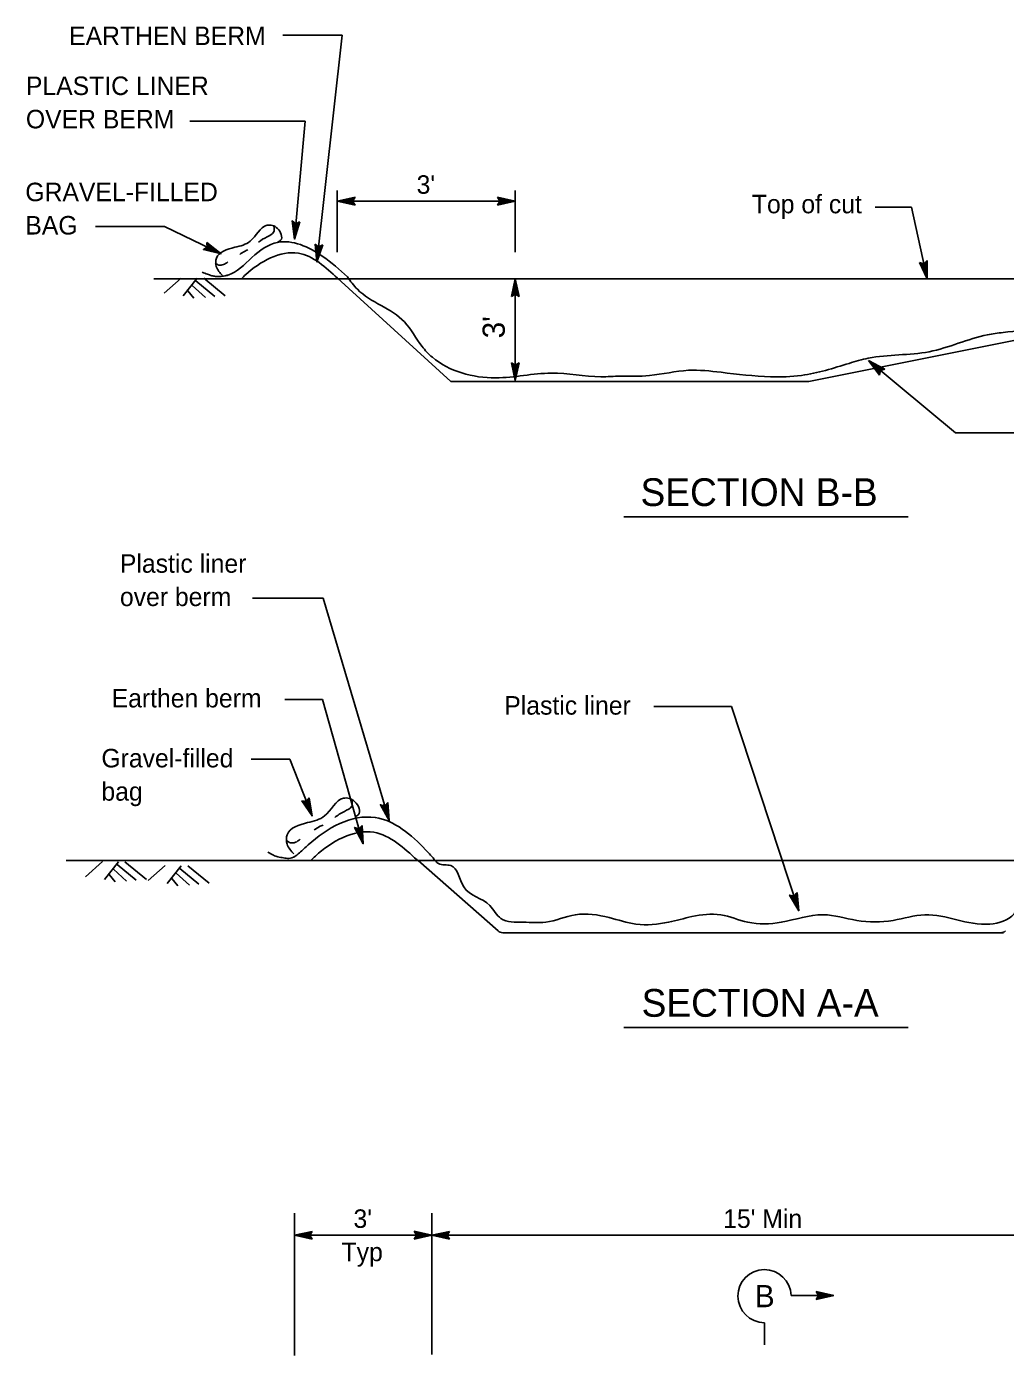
# Model space of a CAD drawing. Extents: x 6708826 to 6711089, y 1868571 to 1869537.
# Drawn here: x 6708825.9 to 6709143.3, y 1869106.3 to 1869537.2 of the extents above; entities that cross this region are included whole.
import ezdxf

# ---------------------------------------------------------------- set-up
doc = ezdxf.new("R2010")
doc.units = 0
for name, color, linetype in [('1 Control', 7, 'Continuous'), ('56 Stg 3 Anno', 7, 'Continuous'), ('57 Undefined', 7, 'Continuous'), ('59 Soundwall Ann', 7, 'Continuous'), ('60 Nongeo Data', 7, 'Continuous')]:
    doc.layers.add(name, color=color, linetype=linetype)

msp = doc.modelspace()

# ---------------------------------------------------------------- linework, layer by layer
at = {"layer": '1 Control'}
for p, q in [((6708911.99, 1869474.17), (6708911.99, 1869474.17)), ((6708914.54, 1869473.94), (6708914.54, 1869473.94)), ((6708912.74, 1869468.32), (6708912.74, 1869468.32)), ((6708883.21, 1869464.88), (6708883.21, 1869464.88)), ((6708884.32, 1869467.19), (6708884.32, 1869467.19)), ((6708888.96, 1869463.54), (6708888.96, 1869463.54)), ((6708917.57, 1869287.05), (6708917.57, 1869287.05)), ((6708915.18, 1869286.11), (6708915.18, 1869286.11)), ((6708940.64, 1869284.86), (6708940.64, 1869284.86)), ((6708943.09, 1869285.59), (6708943.09, 1869285.59)), ((6708918.48, 1869281.22), (6708918.48, 1869281.22)), ((6708934.74, 1869278.11), (6708934.74, 1869278.11)), ((6708943.5, 1869279.7), (6708943.5, 1869279.7)), ((6708932.27, 1869277.41), (6708932.27, 1869277.41)), ((6708935.07, 1869272.22), (6708935.07, 1869272.22)), ((6709073.32, 1869255.54), (6709073.32, 1869255.54)), ((6709075.75, 1869256.34), (6709075.75, 1869256.34)), ((6709076.33, 1869250.47), (6709076.33, 1869250.47))]:
    msp.add_line(p, q, dxfattribs=at)
for points in [[(6708914.54, 1869473.94), (6708912.74, 1869468.32), (6708911.99, 1869474.17), (6708912.31, 1869473.94), (6708912.86, 1869469.65), (6708914.19, 1869473.77), (6708913.83, 1869473.6), (6708912.98, 1869470.96), (6708912.63, 1869473.7), (6708912.95, 1869473.47), (6708913.1, 1869472.28), (6708913.47, 1869473.42), (6708913.19, 1869473.29), (6708911.99, 1869474.17), (6708913.19, 1869473.29)], [(6708884.32, 1869467.19), (6708888.96, 1869463.54), (6708883.21, 1869464.88), (6708883.54, 1869465.1), (6708887.75, 1869464.11), (6708884.36, 1869466.79), (6708884.39, 1869466.4), (6708886.57, 1869464.69), (6708883.87, 1869465.32), (6708884.21, 1869465.53), (6708885.37, 1869465.26), (6708884.43, 1869466), (6708884.46, 1869465.7), (6708883.21, 1869464.88), (6708884.46, 1869465.7)], [(6708917.57, 1869287.05), (6708918.48, 1869281.22), (6708915.18, 1869286.11), (6708915.58, 1869286.04), (6708917.99, 1869282.46), (6708917.33, 1869286.74), (6708917.08, 1869286.42), (6708917.51, 1869283.69), (6708915.97, 1869285.98), (6708916.36, 1869285.91), (6708917.03, 1869284.92), (6708916.84, 1869286.11), (6708916.65, 1869285.86), (6708915.18, 1869286.11), (6708916.65, 1869285.86)], [(6708943.09, 1869285.59), (6708943.5, 1869279.7), (6708940.64, 1869284.86), (6708941.02, 1869284.76), (6708943.12, 1869280.98), (6708942.83, 1869285.3), (6708942.56, 1869285.01), (6708942.75, 1869282.25), (6708941.41, 1869284.66), (6708941.79, 1869284.56), (6708942.37, 1869283.52), (6708942.29, 1869284.72), (6708942.08, 1869284.49), (6708940.64, 1869284.86), (6708942.08, 1869284.49)], [(6708934.74, 1869278.11), (6708935.07, 1869272.22), (6708932.27, 1869277.42), (6708932.66, 1869277.31), (6708934.7, 1869273.5), (6708934.47, 1869277.82), (6708934.2, 1869277.54), (6708934.35, 1869274.77), (6708933.04, 1869277.21), (6708933.42, 1869277.1), (6708933.99, 1869276.05), (6708933.92, 1869277.25), (6708933.71, 1869277.02), (6708932.27, 1869277.42), (6708933.71, 1869277.02)], [(6709075.75, 1869256.34), (6709076.33, 1869250.47), (6709073.32, 1869255.54), (6709073.7, 1869255.45), (6709075.91, 1869251.74), (6709075.49, 1869256.04), (6709075.23, 1869255.75), (6709075.5, 1869252.99), (6709074.09, 1869255.37), (6709074.48, 1869255.28), (6709075.09, 1869254.25), (6709074.97, 1869255.45), (6709074.77, 1869255.21), (6709073.32, 1869255.54), (6709074.77, 1869255.21)]]:
    msp.add_lwpolyline(points, close=True, dxfattribs=at)
for points in [[(6708891.62, 1869456.71), (6708888.99, 1869456.17), (6708887.13, 1869456.17), (6708886.01, 1869456.42), (6708884.52, 1869456.92), (6708882.78, 1869457.54)], [(6708912.89, 1869268.11), (6708910.93, 1869267.44), (6708909.23, 1869267.61), (6708907.37, 1869267.95), (6708906.01, 1869268.46), (6708904.15, 1869269.47)]]:
    msp.add_spline(points, degree=3, dxfattribs=at)
at = {"layer": '56 Stg 3 Anno'}
for p, q in [((6708909.02, 1869534.44), (6708928.28, 1869534.44)), ((6708928.28, 1869534.44), (6708920.06, 1869460.81)), ((6708878.78, 1869506.53), (6708916.19, 1869506.53)), ((6708916.19, 1869506.53), (6708912.74, 1869468.32)), ((6708926.64, 1869464.09), (6708926.64, 1869484.01)), ((6708926.64, 1869480.58), (6708932.4, 1869481.86)), ((6708927.97, 1869480.58), (6708932.17, 1869481.51)), ((6708929.29, 1869480.58), (6708932, 1869481.18)), ((6708930.62, 1869480.58), (6708931.78, 1869480.83)), ((6708932.4, 1869481.86), (6708931.63, 1869480.58)), ((6708932.4, 1869481.86), (6708932.4, 1869481.86)), ((6708979.39, 1869480.58), (6708978.62, 1869481.87)), ((6708978.62, 1869481.87), (6708978.62, 1869481.87)), ((6708978.62, 1869481.87), (6708984.38, 1869480.58)), ((6708978.83, 1869481.52), (6708983.06, 1869480.58)), ((6708979.05, 1869481.18), (6708981.73, 1869480.58)), ((6708979.22, 1869480.85), (6708980.4, 1869480.58)), ((6708984.38, 1869464.09), (6708984.38, 1869484.01)), ((6708926.64, 1869480.58), (6708984.38, 1869480.58)), ((6708932.4, 1869479.29), (6708926.64, 1869480.58)), ((6708926.64, 1869480.58), (6708926.64, 1869480.58)), ((6708932.19, 1869479.64), (6708927.96, 1869480.58)), ((6708931.96, 1869479.98), (6708929.29, 1869480.58)), ((6708931.8, 1869480.31), (6708930.62, 1869480.58)), ((6708931.63, 1869480.58), (6708932.4, 1869479.29)), ((6708932.4, 1869479.29), (6708932.4, 1869479.29)), ((6708984.38, 1869480.58), (6708978.62, 1869479.3)), ((6708978.62, 1869479.3), (6708979.39, 1869480.58)), ((6708978.62, 1869479.3), (6708978.62, 1869479.3)), ((6708983.05, 1869480.58), (6708978.85, 1869479.65)), ((6708981.73, 1869480.58), (6708979.02, 1869479.98)), ((6708980.4, 1869480.58), (6708979.24, 1869480.33)), ((6708984.38, 1869480.58), (6708984.38, 1869480.58)), ((6709101.13, 1869478.66), (6709112.86, 1869478.66)), ((6709112.86, 1869478.66), (6709117.97, 1869455.4)), ((6708848.2, 1869472.33), (6708870.66, 1869472.33)), ((6708870.66, 1869472.33), (6708888.96, 1869463.54)), ((6708920.06, 1869460.81), (6708919.43, 1869466.67)), ((6708919.43, 1869466.67), (6708919.43, 1869466.67)), ((6708919.43, 1869466.67), (6708920.61, 1869465.77)), ((6708920.2, 1869462.13), (6708919.75, 1869466.41)), ((6708921.98, 1869466.39), (6708920.06, 1869460.81)), ((6708920.36, 1869463.44), (6708920.06, 1869466.21)), ((6708921.61, 1869466.22), (6708920.21, 1869462.12)), ((6708921.25, 1869466.04), (6708920.36, 1869463.44)), ((6708920.5, 1869464.76), (6708920.38, 1869465.94)), ((6708920.9, 1869465.9), (6708920.5, 1869464.76)), ((6708920.61, 1869465.77), (6708921.98, 1869466.39)), ((6708921.98, 1869466.39), (6708921.98, 1869466.39)), ((6708920.06, 1869460.81), (6708920.06, 1869460.81)), ((6709117.97, 1869455.4), (6709115.49, 1869460.75)), ((6709115.49, 1869460.75), (6709115.49, 1869460.75)), ((6709115.49, 1869460.75), (6709116.9, 1869460.28)), ((6709117.68, 1869456.7), (6709115.87, 1869460.61)), ((6709117.4, 1869457.99), (6709116.23, 1869460.51)), ((6709117.12, 1869459.29), (6709116.62, 1869460.36)), ((6709116.9, 1869460.28), (6709117.99, 1869461.3)), ((6709117.12, 1869460.5), (6709117.12, 1869459.29)), ((6709117.41, 1869460.73), (6709117.4, 1869457.99)), ((6709117.7, 1869461.03), (6709117.69, 1869456.69)), ((6709117.99, 1869461.3), (6709117.97, 1869455.4)), ((6709117.99, 1869461.3), (6709117.99, 1869461.3)), ((6708983.1, 1869449.64), (6708984.38, 1869455.4)), ((6708984.38, 1869422.39), (6708984.38, 1869455.4)), ((6708984.38, 1869455.4), (6708984.38, 1869455.4)), ((6708984.38, 1869455.4), (6708985.66, 1869449.64)), ((6709117.97, 1869455.4), (6709117.97, 1869455.4)), ((6708983.44, 1869449.85), (6708984.38, 1869454.08)), ((6708983.78, 1869450.07), (6708984.38, 1869452.75)), ((6708984.12, 1869450.24), (6708984.38, 1869451.42)), ((6708984.38, 1869452.75), (6708984.98, 1869450.04)), ((6708984.38, 1869451.42), (6708984.64, 1869450.26)), ((6708984.39, 1869454.07), (6708985.31, 1869449.87)), ((6708984.38, 1869450.41), (6708983.1, 1869449.64)), ((6708983.1, 1869449.64), (6708983.1, 1869449.64)), ((6708985.66, 1869449.64), (6708984.38, 1869450.41)), ((6708985.66, 1869449.64), (6708985.66, 1869449.64)), ((6709127.18, 1869405.43), (6709098.99, 1869428.9)), ((6709102.55, 1869424.19), (6709098.99, 1869428.9)), ((6709098.99, 1869428.9), (6709098.99, 1869428.9)), ((6709098.99, 1869428.9), (6709104.21, 1869426.15)), ((6708984.38, 1869427.38), (6708983.1, 1869428.15)), ((6708983.1, 1869428.15), (6708983.1, 1869428.15)), ((6708983.1, 1869428.15), (6708984.38, 1869422.39)), ((6708983.44, 1869427.94), (6708984.38, 1869423.72)), ((6708983.78, 1869427.72), (6708984.38, 1869425.04)), ((6708984.12, 1869427.55), (6708984.38, 1869426.37)), ((6708984.38, 1869422.39), (6708985.66, 1869428.15)), ((6708985.66, 1869428.15), (6708984.38, 1869427.38)), ((6708984.38, 1869425.04), (6708984.98, 1869427.76)), ((6708984.38, 1869426.37), (6708984.64, 1869427.53)), ((6708984.39, 1869423.73), (6708985.31, 1869427.93)), ((6708985.66, 1869428.15), (6708985.66, 1869428.15)), ((6709102.61, 1869424.59), (6709100, 1869428.04)), ((6709100.01, 1869428.04), (6709103.81, 1869426.03)), ((6709102.66, 1869425), (6709101.01, 1869427.18)), ((6709101.01, 1869427.18), (6709103.47, 1869425.89)), ((6709102.75, 1869425.36), (6709102.02, 1869426.32)), ((6709102.02, 1869426.32), (6709103.07, 1869425.77)), ((6709102.8, 1869425.67), (6709102.55, 1869424.19)), ((6709104.21, 1869426.15), (6709102.8, 1869425.67)), ((6709104.21, 1869426.15), (6709104.21, 1869426.15)), ((6708984.38, 1869422.39), (6708984.38, 1869422.39)), ((6709102.55, 1869424.19), (6709102.55, 1869424.19)), ((6709127.18, 1869405.43), (6709155.5, 1869405.43)), ((6708899.18, 1869351.88), (6708922.03, 1869351.88)), ((6708922.03, 1869351.88), (6708943.5, 1869279.7)), ((6708909.69, 1869319), (6708921.85, 1869319)), ((6708921.85, 1869319), (6708935.07, 1869272.22)), ((6709029.28, 1869316.66), (6709054.5, 1869316.66)), ((6709054.5, 1869316.66), (6709076.33, 1869250.47)), ((6708898.74, 1869299.64), (6708911.22, 1869299.64)), ((6708911.22, 1869299.64), (6708918.48, 1869281.22)), ((6708912.74, 1869106.26), (6708912.74, 1869152.41)), ((6708957.34, 1869106.58), (6708957.34, 1869152.41)), ((6708912.74, 1869145.21), (6708918.5, 1869146.49)), ((6708912.74, 1869145.21), (6708957.34, 1869145.21)), ((6708918.5, 1869143.92), (6708912.74, 1869145.21)), ((6708912.74, 1869145.21), (6708912.74, 1869145.21)), ((6708918.29, 1869144.27), (6708914.06, 1869145.21)), ((6708914.07, 1869145.21), (6708918.27, 1869146.14)), ((6708915.39, 1869145.21), (6708918.1, 1869145.81)), ((6708918.07, 1869144.61), (6708915.39, 1869145.21)), ((6708916.72, 1869145.21), (6708917.88, 1869145.46)), ((6708917.9, 1869144.94), (6708916.72, 1869145.21)), ((6708918.5, 1869146.49), (6708917.73, 1869145.21)), ((6708917.73, 1869145.21), (6708918.5, 1869143.92)), ((6708918.5, 1869146.49), (6708918.5, 1869146.49)), ((6708952.35, 1869145.21), (6708951.58, 1869146.5)), ((6708951.58, 1869146.5), (6708951.58, 1869146.5)), ((6708951.58, 1869146.5), (6708957.34, 1869145.21)), ((6708957.34, 1869145.21), (6708951.58, 1869143.93)), ((6708951.58, 1869143.93), (6708952.35, 1869145.21)), ((6708951.79, 1869146.15), (6708956.01, 1869145.21)), ((6708956, 1869145.21), (6708951.8, 1869144.28)), ((6708954.69, 1869145.21), (6708951.97, 1869144.61)), ((6708952.01, 1869145.81), (6708954.69, 1869145.21)), ((6708952.18, 1869145.48), (6708953.36, 1869145.21)), ((6708953.36, 1869145.21), (6708952.2, 1869144.96)), ((6708957.34, 1869145.21), (6708963.1, 1869146.49)), ((6708957.34, 1869145.21), (6709173.02, 1869145.21)), ((6708957.34, 1869145.21), (6708957.34, 1869145.21)), ((6708963.1, 1869143.92), (6708957.34, 1869145.21)), ((6708957.34, 1869145.21), (6708957.34, 1869145.21)), ((6708962.89, 1869144.27), (6708958.66, 1869145.21)), ((6708958.67, 1869145.21), (6708962.87, 1869146.14)), ((6708959.99, 1869145.21), (6708962.7, 1869145.81)), ((6708962.67, 1869144.61), (6708959.99, 1869145.21)), ((6708961.32, 1869145.21), (6708962.48, 1869145.46)), ((6708962.5, 1869144.94), (6708961.32, 1869145.21)), ((6708963.1, 1869146.49), (6708962.33, 1869145.21)), ((6708962.33, 1869145.21), (6708963.1, 1869143.92)), ((6708963.1, 1869146.49), (6708963.1, 1869146.49)), ((6708918.5, 1869143.92), (6708918.5, 1869143.92)), ((6708951.58, 1869143.93), (6708951.58, 1869143.93)), ((6708963.1, 1869143.92), (6708963.1, 1869143.92)), ((6709087.74, 1869125.66), (6709073.81, 1869125.66)), ((6709082.74, 1869125.66), (6709081.97, 1869126.95)), ((6709081.97, 1869126.95), (6709081.97, 1869126.95)), ((6709081.97, 1869126.95), (6709087.74, 1869125.66)), ((6709087.74, 1869125.66), (6709081.98, 1869124.38)), ((6709081.98, 1869124.38), (6709082.74, 1869125.66)), ((6709081.98, 1869124.38), (6709081.98, 1869124.38)), ((6709082.18, 1869126.6), (6709086.41, 1869125.66)), ((6709086.4, 1869125.66), (6709082.2, 1869124.73)), ((6709085.09, 1869125.66), (6709082.37, 1869125.06)), ((6709082.41, 1869126.26), (6709085.09, 1869125.66)), ((6709082.58, 1869125.93), (6709083.76, 1869125.66)), ((6709083.76, 1869125.66), (6709082.6, 1869125.4)), ((6709087.74, 1869125.66), (6709087.74, 1869125.66)), ((6709065.18, 1869116.86), (6709065.18, 1869109.73))]:
    msp.add_line(p, q, dxfattribs=at)
msp.add_arc((6709065.19, 1869125.49), 8.62, 1.113, 269.9585, dxfattribs=at)
at = {"layer": '57 Undefined'}
for p, q in [((6709019.6, 1869378.21), (6709111.8, 1869378.21)), ((6709019.6, 1869212.57), (6709111.8, 1869212.57))]:
    msp.add_line(p, q, dxfattribs=at)
at = {"layer": '59 Soundwall Ann'}
for p, q in [((6708876.02, 1869455.67), (6708870.54, 1869450.8)), ((6708881.22, 1869455.64), (6708876.7, 1869449.89)), ((6708880.77, 1869454.78), (6708886.96, 1869449.68)), ((6708883.32, 1869455.62), (6708890.25, 1869449.92)), ((6708878.14, 1869451.54), (6708880.12, 1869449.11)), ((6708879.64, 1869453.19), (6708883.87, 1869449.34)), ((6708850.5, 1869266.39), (6708845.02, 1869261.52)), ((6708855.69, 1869266.35), (6708851.18, 1869260.61)), ((6708855.25, 1869265.49), (6708861.44, 1869260.4)), ((6708857.8, 1869266.33), (6708864.73, 1869260.63)), ((6708852.62, 1869262.26), (6708854.6, 1869259.83)), ((6708854.12, 1869263.91), (6708858.34, 1869260.06)), ((6708870.84, 1869265.12), (6708865.36, 1869260.24)), ((6708876.03, 1869265.08), (6708871.51, 1869259.34)), ((6708872.95, 1869260.98), (6708874.93, 1869258.56)), ((6708874.45, 1869262.63), (6708878.68, 1869258.79)), ((6708875.58, 1869264.22), (6708881.77, 1869259.12)), ((6708878.14, 1869265.06), (6708885.06, 1869259.36))]:
    msp.add_line(p, q, dxfattribs=at)
at = {"layer": '60 Nongeo Data'}
for p, q in [((6708867.16, 1869455.4), (6708926.44, 1869455.4)), ((6708926.44, 1869455.4), (6709246.42, 1869455.4)), ((6709079.54, 1869422.13), (6709245.91, 1869455.4)), ((6708963.49, 1869422.13), (6709079.54, 1869422.13)), ((6708838.74, 1869266.71), (6708952.88, 1869266.71)), ((6708952.25, 1869266.71), (6709101.25, 1869266.71)), ((6708952.88, 1869266.71), (6708978.79, 1869243.93)), ((6709100.59, 1869266.71), (6709168.62, 1869266.71)), ((6708980.34, 1869243.35), (6709142.68, 1869243.35)), ((6709141.8, 1869243.35), (6709100.59, 1869243.35))]:
    msp.add_line(p, q, dxfattribs=at)
msp.add_lwpolyline([(6708963.49, 1869422.13), (6708926.73, 1869455.6)], dxfattribs=at)
for centre, start_param, end_param in [((6708980.33, 1869245.69), 5.561991, 6.283185), ((6709141.8, 1869245.69), 0, 0.721194)]:
    msp.add_ellipse(centre, major_axis=(0, -2.34), ratio=0.999991, start_param=start_param, end_param=end_param, dxfattribs=at)
for points in [[(6708889.41, 1869456.44), (6708887.41, 1869459.36), (6708887.45, 1869462.09), (6708893.4, 1869465.62), (6708898.4, 1869467.58), (6708903.9, 1869472.76), (6708907.25, 1869471.75), (6708908.27, 1869467.93), (6708907.4, 1869467.36)], [(6708901.08, 1869467.32), (6708903.88, 1869469.06), (6708906.02, 1869470.6), (6708906.08, 1869472.38)], [(6708929.94, 1869456.04), (6708921.77, 1869462.78), (6708907.28, 1869467.24), (6708898.97, 1869462.35), (6708891.16, 1869456.58), (6708890.61, 1869456.44)], [(6708895.02, 1869463.34), (6708896.56, 1869464.3), (6708897.63, 1869464.77)], [(6708926.95, 1869455.4), (6708926.7, 1869455.63), (6708914.04, 1869463.73), (6708896.94, 1869456.76), (6708895.55, 1869455.44)], [(6708887.08, 1869460.51), (6708888.25, 1869459.88), (6708889.72, 1869460.02), (6708891.11, 1869460.89)], [(6709018.5, 1869423.89), (6709012.16, 1869423.66), (6708996.07, 1869424.82), (6708977.99, 1869423.29), (6708957.5, 1869429.97), (6708954.14, 1869433.49), (6708948.45, 1869441.44), (6708933.16, 1869452.03), (6708929.94, 1869456.04)], [(6709155.03, 1869439.22), (6709142.61, 1869438.01), (6709137.51, 1869437.25), (6709118.63, 1869431.78), (6709098.86, 1869429.66), (6709092.64, 1869427.99), (6709077.2, 1869424.09), (6709067.17, 1869423.66), (6709051.11, 1869425.1), (6709040.55, 1869425.74), (6709027.92, 1869424.04), (6709018.17, 1869423.86)], [(6708912.57, 1869268.88), (6708910.36, 1869272.11), (6708910.4, 1869275.14), (6708917, 1869279.05), (6708922.53, 1869281.22), (6708928.63, 1869286.96), (6708932.34, 1869285.84), (6708933.47, 1869281.61), (6708932.5, 1869280.97)], [(6708925.85, 1869280.76), (6708928.94, 1869282.69), (6708931.32, 1869284.39), (6708931.38, 1869286.36)], [(6708958.51, 1869266.68), (6708955.27, 1869270.26), (6708938.94, 1869280.71), (6708917.24, 1869271.86), (6708914.39, 1869269.23), (6708912.55, 1869267.86)], [(6708919.13, 1869276.69), (6708920.84, 1869277.75), (6708922.02, 1869278.27)], [(6708952.82, 1869266.71), (6708952.53, 1869266.97), (6708938.51, 1869275.93), (6708919.56, 1869268.22), (6708918.02, 1869266.75)], [(6708910.16, 1869273.21), (6708911.46, 1869272.52), (6708913.08, 1869272.67), (6708914.63, 1869273.64)], [(6709163.61, 1869266.78), (6709161.57, 1869264.84), (6709157.64, 1869259.41), (6709150.39, 1869255.79), (6709146.16, 1869249.46), (6709138.31, 1869246.15), (6709117.17, 1869249.16), (6709106.9, 1869247.35), (6709095.12, 1869247.35), (6709084.24, 1869249.16), (6709070.65, 1869246.75), (6709059.78, 1869246.75), (6709051.02, 1869249.16), (6709041.66, 1869248.56), (6709034.11, 1869246.75), (6709023.53, 1869246.15), (6709014.78, 1869248.26), (6709003.9, 1869249.16), (6708994.24, 1869246.75), (6708986.99, 1869246.75), (6708979.74, 1869247.96), (6708976.12, 1869252.18), (6708967.66, 1869258.2), (6708963.43, 1869265.14), (6708959.5, 1869265.74), (6708958.51, 1869266.68)]]:
    msp.add_spline(points, degree=3, dxfattribs=at)

# ---------------------------------------------------------------- texts
at = {"layer": '57 Undefined'}
for s, height, p in [('EARTHEN BERM', 6, (6708839.68, 1869531.21)), ('PLASTIC LINER', 6, (6708825.66, 1869515.01)), ('OVER BERM', 6, (6708825.66, 1869504.21)), ('GRAVEL-FILLED ', 6, (6708825.48, 1869480.58)), ("3'", 6, (6708952.38, 1869482.98)), ('Top of cut', 6, (6709061.11, 1869476.66)), ('BAG', 6, (6708825.48, 1869469.78)), ('SECTION B-B', 9, (6709025, 1869381.72)), ('Plastic liner', 6, (6708856.16, 1869360.08)), ('over berm', 6, (6708856.16, 1869349.28)), ('Earthen berm', 6, (6708853.47, 1869316.41)), ('Plastic liner', 6, (6708980.82, 1869314.07)), ('Gravel-filled', 6, (6708850.15, 1869296.96)), ('bag', 6, (6708850.15, 1869286.16)), ('SECTION A-A', 9, (6709025.35, 1869216.08)), ("3'", 6, (6708931.91, 1869147.61)), ("15' Min", 6, (6709051.81, 1869147.61)), ('Typ', 6, (6708928.05, 1869136.81)), ('B', 7.21, (6709062.06, 1869121.89))]:
    msp.add_text(s, height=height, dxfattribs=at).set_placement(p)
msp.add_text("3'", height=7.2, rotation=90, dxfattribs=at).set_placement((6708980.98, 1869436.1))

doc.saveas('drawing.dxf')
